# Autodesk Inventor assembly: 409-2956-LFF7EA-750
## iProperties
Created: 2010-06
Part Number: 409-2956-LFF7EA-750
Document SubType Name: Weldment
Designer: S. Boerckel
Mass: 6927.41 g
Surface Area: 2787.66 cm^2
Volume: 881.798 cm^3
Density: 7.856 g/cm^3
Description: RECIRCULATION SPOOL
Weld Material: Welded Steel Mild
User Status: WELD
Material: WEDLMENT
SMR: =<MATERIAL>
Author: S. Boerckel
Revision Number: B
Subject: DEMIN WATER FORWARDING PUMP SKID-7EA
